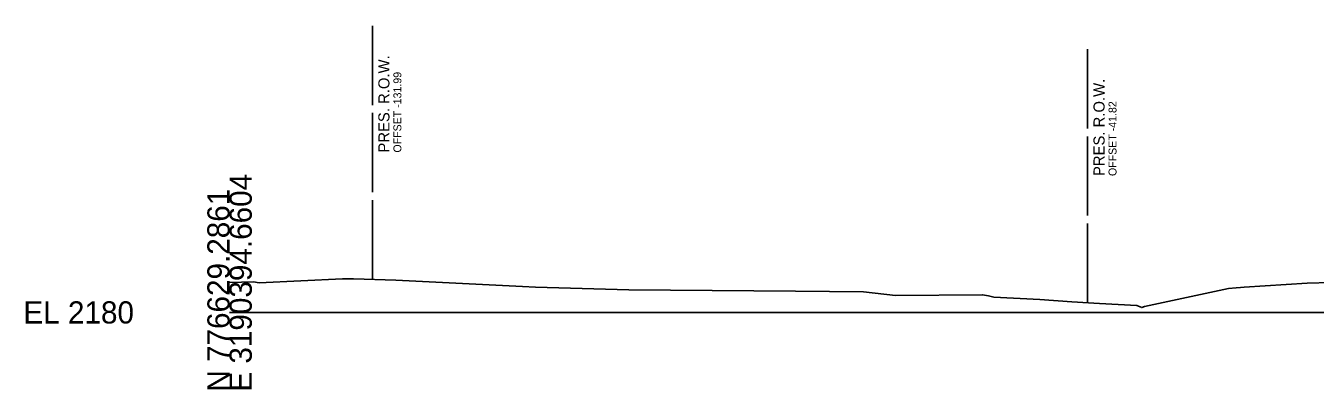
# Model space of a CAD drawing. Extents: x -26 to 303, y -10 to 13517.
# Drawn here: x -25.7 to 136.9, y 8990.3 to 9036.2 of the extents above; entities that cross this region are included whole.
import ezdxf

# ---------------------------------------------------------------- set-up
doc = ezdxf.new("R2010")
doc.units = 0
for name, color, linetype in [('DESIGN - SHEET - Light Grid', 7, 'Continuous'), ('SURVEY - GROUND - Top of Ground', 7, 'Continuous'), ('SURVEY - PROPERTY - ROW Lines', 7, 'Continuous'), ('SURVEY - PROPERTY - ROW Lines Text', 7, 'Continuous')]:
    doc.layers.add(name, color=color, linetype=linetype)

msp = doc.modelspace()

# ---------------------------------------------------------------- linework, layer by layer
at = {"layer": 'DESIGN - SHEET - Light Grid'}
msp.add_line((0, 9000), (150, 9000), dxfattribs=at)
at = {"layer": 'SURVEY - GROUND - Top of Ground'}
msp.add_lwpolyline([(0, 9003.77), (3.03, 9003.84), (3.73, 9003.73), (14.23, 9004.23), (15.64, 9004.25), (20.95, 9004.08), (36.95, 9003.27), (38.59, 9003.19), (50.35, 9002.85), (71.37, 9002.67), (79.93, 9002.6), (83.95, 9002.15), (94.94, 9002.23), (95.69, 9002.08), (96.38, 9001.94), (102.17, 9001.61), (106.19, 9001.33), (109.69, 9001.11), (114.39, 9000.88), (115.02, 9000.62), (115.37, 9000.74), (125.97, 9003.02), (126.9, 9003.11), (127.47, 9003.15), (127.92, 9003.17), (135.86, 9003.71), (138.84, 9003.77)], dxfattribs=at)
at = {"layer": 'SURVEY - PROPERTY - ROW Lines'}
for p, q in [((18.01, 9026.17), (18.01, 9036.17)), ((108.18, 9023.21), (108.18, 9033.21)), ((18.01, 9015.17), (18.01, 9025.17)), ((108.18, 9012.21), (108.18, 9022.21)), ((18.01, 9004.17), (18.01, 9014.17)), ((108.18, 9001.21), (108.18, 9011.21))]:
    msp.add_line(p, q, dxfattribs=at)

# ---------------------------------------------------------------- texts
at = {"layer": 'DESIGN - SHEET - Light Grid'}
for s, p in [('E 3190394.6604', (2.8, 8990)), ('N 776629.2861', (0, 8990))]:
    msp.add_text(s, height=2.8, rotation=90, dxfattribs=at).set_placement(p)
msp.add_text('EL 2180', height=2.8, dxfattribs=at).set_placement((-26, 8998.6))
at = {"layer": 'SURVEY - PROPERTY - ROW Lines Text'}
for s, height, p in [('PRES. R.O.W.', 1.4, (20.16, 9020.17)), ('OFFSET -131.99', 1, (21.66, 9020.17)), ('PRES. R.O.W.', 1.4, (110.33, 9017.21)), ('OFFSET -41.82', 1, (111.83, 9017.21))]:
    msp.add_text(s, height=height, rotation=90, dxfattribs=at).set_placement(p)

doc.saveas('drawing.dxf')
